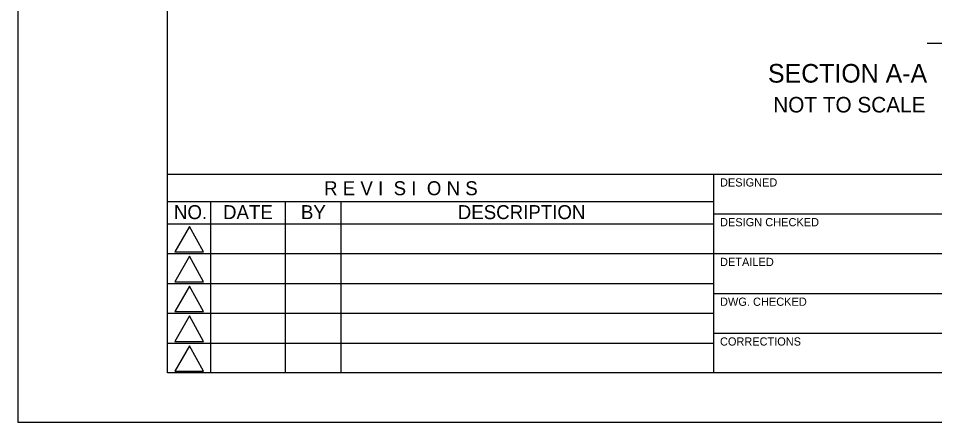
# Model space of a CAD drawing. Extents: x 0 to 136, y 0 to 94.
# Drawn here: x 0 to 36.89, y 0 to 16.27 of the extents above; entities that cross this region are included whole.
import ezdxf

# ---------------------------------------------------------------- set-up
doc = ezdxf.new("R2010")
doc.units = 0
for name, color, linetype in [('BORDER_ANNO_Cutsheet', 7, 'Continuous'), ('BRDG_ANNO_Anno-Sheet', 7, 'Continuous'), ('BRDG_ANNO_General-Notes', 7, 'Continuous'), ('BRDG_BASE_Active-Point', 7, 'Continuous'), ('BRDG_BASE_Obj-Line', 7, 'Continuous')]:
    doc.layers.add(name, color=color, linetype=linetype)

msp = doc.modelspace()

# ---------------------------------------------------------------- linework, layer by layer
at = {"layer": 'BORDER_ANNO_Cutsheet'}
msp.add_lwpolyline([(0, 88), (136, 88), (136, 0), (0, 0)], close=True, dxfattribs=at)
at = {"layer": 'BRDG_ANNO_Anno-Sheet'}
for p, q in [((6, 10), (77, 10)), ((28, 2), (28, 10)), ((6, 8.9), (28, 8.9)), ((7.75, 2), (7.75, 8.9)), ((10.75, 2), (10.75, 8.9)), ((13, 2), (13, 8.877)), ((28, 8.4), (38, 8.4)), ((5.99, 8), (28, 8)), ((5.99, 6.8), (28, 6.8)), ((28, 6.8), (38, 6.8)), ((5.99, 5.6), (28, 5.6)), ((28, 5.2), (38, 5.2)), ((5.99, 4.4), (28, 4.4)), ((28, 3.6), (38, 3.6)), ((5.99, 3.2), (28, 3.2))]:
    msp.add_line(p, q, dxfattribs=at)
msp.add_lwpolyline([(6, 86), (134, 86), (134, 2), (6, 2)], close=True, dxfattribs=at)
for points in [[(6.89, 7.897), (6.297, 6.87), (7.457, 6.87), (6.89, 7.897)], [(6.89, 6.697), (6.297, 5.67), (7.457, 5.67), (6.89, 6.697)], [(6.89, 5.497), (6.297, 4.47), (7.457, 4.47), (6.89, 5.497)], [(6.89, 4.297), (6.297, 3.27), (7.457, 3.27), (6.89, 4.297)], [(6.89, 3.097), (6.297, 2.07), (7.457, 2.07), (6.89, 3.097)]]:
    msp.add_lwpolyline(points, dxfattribs=at)
at = {"layer": 'BRDG_BASE_Active-Point'}
msp.add_line((0, 0), (0, 0), dxfattribs=at)
at = {"layer": 'BRDG_BASE_Obj-Line'}
msp.add_line((38.856, 15.253), (36.584, 15.253), dxfattribs=at)

# ---------------------------------------------------------------- texts
at = {"layer": 'BRDG_ANNO_Anno-Sheet'}
for s, height, p in [('R E V I  S I  O N S', 0.5625, (12.309, 9.15)), ('DESIGNED', 0.33, (28.25, 9.5)), ('NO.', 0.5625, (6.266, 8.188)), ('DATE', 0.5625, (8.24, 8.188)), ('BY', 0.5625, (11.377, 8.188)), ('DESCRIPTION', 0.5625, (17.691, 8.188)), ('DESIGN CHECKED', 0.33124, (28.25, 7.9)), ('DETAILED', 0.3312, (28.25, 6.3)), ('DWG. CHECKED', 0.33124, (28.25, 4.7)), ('CORRECTIONS', 0.33, (28.25, 3.1))]:
    msp.add_text(s, height=height, dxfattribs=at).set_placement(p)
at = {"layer": 'BRDG_ANNO_General-Notes'}
for s, height, p in [('SECTION A-A', 0.75, (30.181, 13.679)), ('NOT TO SCALE', 0.625, (30.392, 12.479))]:
    msp.add_text(s, height=height, dxfattribs=at).set_placement(p)

doc.saveas('drawing.dxf')
